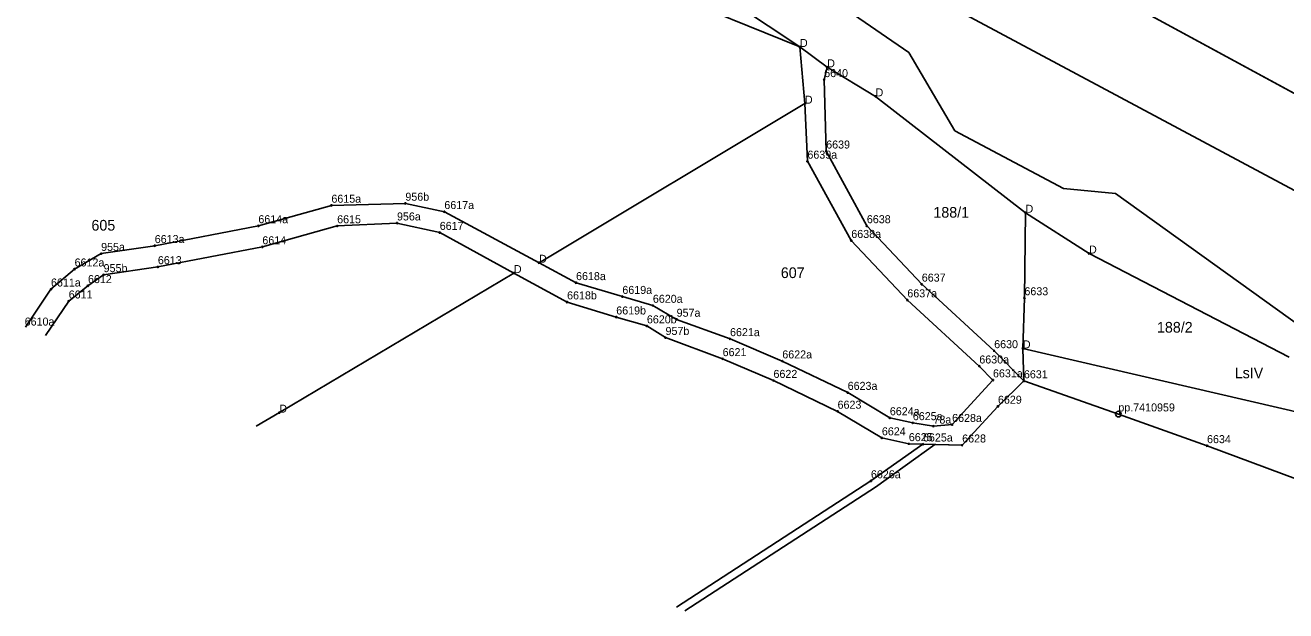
# Model space of a CAD drawing. Extents: x 7465393 to 7466459, y 5491258 to 5492404.
# Drawn here: x 7466057.8 to 7466235, y 5491369 to 5491451.3 of the extents above; entities that cross this region are included whole.
import ezdxf

# ---------------------------------------------------------------- set-up
doc = ezdxf.new("R2010")
doc.units = 0
for name, color, linetype in [('202-punkt graniczny', 7, 'Continuous'), ('202-punkt graniczny-Atr103', 7, 'Continuous'), ('203-punkt graniczny', 7, 'Continuous'), ('203-punkt graniczny-Atr103', 7, 'Continuous'), ('209-oznaczenie konturu klasyfikacyjnego', 7, 'Continuous'), ('211-numer działki ewidencyjnej', 7, 'Continuous'), ('217-kontur klasyfikacyjny', 7, 'Continuous'), ('218-kontur użytku gruntowego', 7, 'Continuous'), ('219-działka ewidencyjna', 7, 'Continuous')]:
    doc.layers.add(name, color=color, linetype=linetype)

# ---------------------------------------------------------------- blocks, each defined once
blk = doc.blocks.new('203')
blk.add_circle((0, 0), 0.09)
blk = doc.blocks.new('202')
blk.add_circle((0, 0), 0.4)

msp = doc.modelspace()

# ---------------------------------------------------------------- linework, layer by layer
at = {"layer": '217-kontur klasyfikacyjny'}
for points in [[(7466166.73, 5491448.28), (7466148.91, 5491460.14)], [(7466208.93, 5491456.57), (7466244.38, 5491437.34)], [(7466167.43, 5491440.31), (7466166.73, 5491448.28)], [(7466170.57, 5491445.42), (7466170.14, 5491443.67)], [(7466177.37, 5491441.33), (7466170.57, 5491445.42)], [(7466170.14, 5491443.67), (7466170.42, 5491433.63)], [(7466167.78, 5491432.2), (7466167.43, 5491440.31)], [(7466198.45, 5491424.97), (7466177.37, 5491441.33)], [(7466170.42, 5491433.63), (7466176.14, 5491423.12)], [(7466173.95, 5491421.06), (7466167.78, 5491432.2)], [(7466090.58, 5491423.12), (7466100.85, 5491426)], [(7466100.85, 5491426), (7466111.25, 5491426.28)], [(7466111.25, 5491426.28), (7466116.73, 5491425.11)], [(7466116.73, 5491425.11), (7466130.04, 5491417.94)], [(7466207.38, 5491419.24), (7466198.45, 5491424.97)], [(7466076.01, 5491420.33), (7466090.58, 5491423.12)], [(7466101.66, 5491423.11), (7466091.14, 5491420.17)], [(7466110.07, 5491423.52), (7466101.66, 5491423.11)], [(7466116.08, 5491422.18), (7466110.07, 5491423.52)], [(7466126.51, 5491416.49), (7466116.08, 5491422.18)], [(7466176.14, 5491423.12), (7466183.86, 5491414.91)], [(7466068.47, 5491419.22), (7466076.01, 5491420.33)], [(7466091.14, 5491420.17), (7466076.45, 5491417.36)], [(7466181.83, 5491412.7), (7466173.95, 5491421.06)], [(7466064.74, 5491417.05), (7466068.47, 5491419.22)], [(7466235.52, 5491404.67), (7466207.38, 5491419.24)], [(7466061.42, 5491414.22), (7466064.74, 5491417.05)], [(7466076.45, 5491417.36), (7466068.82, 5491416.24)], [(7466130.04, 5491417.94), (7466135.25, 5491415.13)], [(7466068.82, 5491416.24), (7466066.62, 5491414.71)], [(7466133.99, 5491412.41), (7466126.51, 5491416.49)], [(7466135.25, 5491415.13), (7466141.76, 5491413.18)], [(7466183.86, 5491414.91), (7466194.04, 5491405.56)], [(7466057.83, 5491408.9), (7466061.42, 5491414.22)], [(7466066.62, 5491414.71), (7466063.91, 5491412.54)], [(7466141.76, 5491413.18), (7466146.05, 5491411.93)], [(7466063.91, 5491412.54), (7466060.64, 5491407.69)], [(7466140.9, 5491410.3), (7466133.99, 5491412.41)], [(7466146.05, 5491411.93), (7466149.39, 5491409.97)], [(7466191.95, 5491403.4), (7466181.83, 5491412.7)], [(7466145.21, 5491409.05), (7466140.9, 5491410.3)], [(7466149.39, 5491409.97), (7466156.9, 5491407.24)], [(7466147.83, 5491407.41), (7466145.21, 5491409.05)], [(7466155.86, 5491404.43), (7466147.83, 5491407.41)], [(7466156.9, 5491407.24), (7466164.25, 5491404.11)], [(7466163.01, 5491401.38), (7466155.86, 5491404.43)], [(7466194.04, 5491405.56), (7466198.22, 5491401.32)], [(7466164.25, 5491404.11), (7466173.44, 5491399.69)], [(7466193.87, 5491401.45), (7466191.95, 5491403.4)], [(7466172.02, 5491397.05), (7466163.01, 5491401.38)], [(7466188.13, 5491395.18), (7466193.87, 5491401.45)], [(7466198.22, 5491401.32), (7466211.5, 5491396.66)], [(7466173.44, 5491399.69), (7466179.37, 5491396.13)], [(7466178.25, 5491393.31), (7466172.02, 5491397.05)], [(7466179.37, 5491396.13), (7466182.6, 5491395.43)], [(7466182.6, 5491395.43), (7466185.5, 5491394.96)], [(7466211.5, 5491396.66), (7466223.97, 5491392.21)], [(7466185.5, 5491394.96), (7466188.13, 5491395.18)], [(7466176.71, 5491387.27), (7466184.03, 5491392.43)], [(7466182.04, 5491392.48), (7466178.25, 5491393.31)], [(7466184.03, 5491392.43), (7466182.04, 5491392.48)], [(7466223.97, 5491392.21), (7466240.84, 5491385.94)], [(7466149.35, 5491369.53), (7466176.71, 5491387.27)]]:
    msp.add_lwpolyline(points, dxfattribs=at)
at = {"layer": '218-kontur użytku gruntowego'}
for points in [[(7466243.1, 5491424.43), (7466171.64, 5491462.69)], [(7466166.73, 5491448.28), (7466148.91, 5491460.14)], [(7466208.93, 5491456.57), (7466244.38, 5491437.34)], [(7466173.49, 5491453.36), (7466182.05, 5491447.52)], [(7466170.57, 5491445.42), (7466166.73, 5491448.28)], [(7466166.73, 5491448.28), (7466167.43, 5491440.31)], [(7466182.05, 5491447.52), (7466188.53, 5491436.49)], [(7466170.57, 5491445.42), (7466170.14, 5491443.67)], [(7466177.37, 5491441.33), (7466170.57, 5491445.42)], [(7466170.14, 5491443.67), (7466170.42, 5491433.63)], [(7466167.43, 5491440.31), (7466167.78, 5491432.2)], [(7466198.45, 5491424.97), (7466177.37, 5491441.33)], [(7466188.53, 5491436.49), (7466203.8, 5491428.37)], [(7466170.42, 5491433.63), (7466176.14, 5491423.12)], [(7466167.78, 5491432.2), (7466173.95, 5491421.06)], [(7466203.8, 5491428.37), (7466211.1, 5491427.7)], [(7466211.1, 5491427.7), (7466239.05, 5491407.62)], [(7466100.85, 5491426), (7466090.58, 5491423.12)], [(7466111.25, 5491426.28), (7466100.85, 5491426)], [(7466116.73, 5491425.11), (7466111.25, 5491426.28)], [(7466130.04, 5491417.94), (7466116.73, 5491425.11)], [(7466207.38, 5491419.24), (7466198.45, 5491424.97)], [(7466090.58, 5491423.12), (7466076.01, 5491420.33)], [(7466101.66, 5491423.11), (7466091.14, 5491420.17)], [(7466110.07, 5491423.52), (7466101.66, 5491423.11)], [(7466116.08, 5491422.18), (7466110.07, 5491423.52)], [(7466126.51, 5491416.49), (7466116.08, 5491422.18)], [(7466176.14, 5491423.12), (7466183.86, 5491414.91)], [(7466076.01, 5491420.33), (7466068.47, 5491419.22)], [(7466091.14, 5491420.17), (7466076.45, 5491417.36)], [(7466173.95, 5491421.06), (7466181.83, 5491412.7)], [(7466068.47, 5491419.22), (7466064.74, 5491417.05)], [(7466235.52, 5491404.67), (7466207.38, 5491419.24)], [(7466064.74, 5491417.05), (7466061.42, 5491414.22)], [(7466076.45, 5491417.36), (7466068.82, 5491416.24)], [(7466135.25, 5491415.13), (7466130.04, 5491417.94)], [(7466068.82, 5491416.24), (7466066.62, 5491414.71)], [(7466133.99, 5491412.41), (7466126.51, 5491416.49)], [(7466141.76, 5491413.18), (7466135.25, 5491415.13)], [(7466183.86, 5491414.91), (7466194.04, 5491405.56)], [(7466061.42, 5491414.22), (7466057.83, 5491408.9)], [(7466066.62, 5491414.71), (7466063.91, 5491412.54)], [(7466146.05, 5491411.93), (7466141.76, 5491413.18)], [(7466063.91, 5491412.54), (7466060.64, 5491407.69)], [(7466140.9, 5491410.3), (7466133.99, 5491412.41)], [(7466149.39, 5491409.97), (7466146.05, 5491411.93)], [(7466181.83, 5491412.7), (7466191.95, 5491403.4)], [(7466145.21, 5491409.05), (7466140.9, 5491410.3)], [(7466156.9, 5491407.24), (7466149.39, 5491409.97)], [(7466147.83, 5491407.41), (7466145.21, 5491409.05)], [(7466155.86, 5491404.43), (7466147.83, 5491407.41)], [(7466164.25, 5491404.11), (7466156.9, 5491407.24)], [(7466163.01, 5491401.38), (7466155.86, 5491404.43)], [(7466194.04, 5491405.56), (7466198.22, 5491401.32)], [(7466173.44, 5491399.69), (7466164.25, 5491404.11)], [(7466191.95, 5491403.4), (7466193.87, 5491401.45)], [(7466172.02, 5491397.05), (7466163.01, 5491401.38)], [(7466193.87, 5491401.45), (7466188.13, 5491395.18)], [(7466198.22, 5491401.32), (7466194.57, 5491397.75)], [(7466179.37, 5491396.13), (7466173.44, 5491399.69)], [(7466194.57, 5491397.75), (7466189.54, 5491392.29)], [(7466178.25, 5491393.31), (7466172.02, 5491397.05)], [(7466182.6, 5491395.43), (7466179.37, 5491396.13)], [(7466185.5, 5491394.96), (7466182.6, 5491395.43)], [(7466188.13, 5491395.18), (7466185.5, 5491394.96)], [(7466184.03, 5491392.43), (7466176.71, 5491387.27)], [(7466177.35, 5491386.39), (7466185.7, 5491392.39)], [(7466182.04, 5491392.48), (7466178.25, 5491393.31)], [(7466184.03, 5491392.43), (7466182.04, 5491392.48)], [(7466185.7, 5491392.39), (7466184.03, 5491392.43)], [(7466189.54, 5491392.29), (7466185.7, 5491392.39)], [(7466176.71, 5491387.27), (7466149.35, 5491369.53)], [(7466150.55, 5491369.01), (7466177.35, 5491386.39)]]:
    msp.add_lwpolyline(points, dxfattribs=at)
at = {"layer": '219-działka ewidencyjna'}
for points in [[(7466171.64, 5491462.69), (7466243.1, 5491424.43)], [(7466147.45, 5491456.12), (7466166.73, 5491448.28)], [(7466208.93, 5491456.57), (7466251.84, 5491433.3)], [(7466166.73, 5491448.28), (7466167.43, 5491440.31)], [(7466166.73, 5491448.28), (7466170.57, 5491445.42)], [(7466170.57, 5491445.42), (7466170.14, 5491443.67)], [(7466170.57, 5491445.42), (7466177.37, 5491441.33)], [(7466170.14, 5491443.67), (7466170.42, 5491433.63)], [(7466130.04, 5491417.94), (7466167.43, 5491440.31)], [(7466167.43, 5491440.31), (7466167.78, 5491432.2)], [(7466177.37, 5491441.33), (7466198.45, 5491424.97)], [(7466170.42, 5491433.63), (7466176.14, 5491423.12)], [(7466167.78, 5491432.2), (7466173.95, 5491421.06)], [(7466090.58, 5491423.12), (7466100.85, 5491426)], [(7466100.85, 5491426), (7466111.25, 5491426.28)], [(7466111.25, 5491426.28), (7466116.73, 5491425.11)], [(7466130.04, 5491417.94), (7466116.73, 5491425.11)], [(7466198.45, 5491424.97), (7466198.29, 5491412.99)], [(7466198.45, 5491424.97), (7466207.38, 5491419.24)], [(7466076.01, 5491420.33), (7466090.58, 5491423.12)], [(7466091.14, 5491420.17), (7466101.66, 5491423.11)], [(7466101.66, 5491423.11), (7466110.07, 5491423.52)], [(7466110.07, 5491423.52), (7466116.08, 5491422.18)], [(7466126.51, 5491416.49), (7466116.08, 5491422.18)], [(7466176.14, 5491423.12), (7466183.86, 5491414.91)], [(7466068.47, 5491419.22), (7466076.01, 5491420.33)], [(7466076.45, 5491417.36), (7466091.14, 5491420.17)], [(7466173.95, 5491421.06), (7466181.83, 5491412.7)], [(7466064.74, 5491417.05), (7466068.47, 5491419.22)], [(7466207.38, 5491419.24), (7466235.52, 5491404.67)], [(7466061.42, 5491414.22), (7466064.74, 5491417.05)], [(7466068.82, 5491416.24), (7466076.45, 5491417.36)], [(7466130.04, 5491417.94), (7466135.25, 5491415.13)], [(7466066.62, 5491414.71), (7466068.82, 5491416.24)], [(7466093.53, 5491396.87), (7466126.51, 5491416.49)], [(7466126.51, 5491416.49), (7466133.99, 5491412.41)], [(7466135.25, 5491415.13), (7466141.76, 5491413.18)], [(7466183.86, 5491414.91), (7466194.04, 5491405.56)], [(7466057.83, 5491408.9), (7466061.42, 5491414.22)], [(7466063.91, 5491412.54), (7466066.62, 5491414.71)], [(7466141.76, 5491413.18), (7466146.05, 5491411.93)], [(7466060.64, 5491407.69), (7466063.91, 5491412.54)], [(7466133.99, 5491412.41), (7466140.9, 5491410.3)], [(7466146.05, 5491411.93), (7466149.39, 5491409.97)], [(7466181.83, 5491412.7), (7466191.95, 5491403.4)], [(7466198.08, 5491405.9), (7466198.29, 5491412.99)], [(7466140.9, 5491410.3), (7466145.21, 5491409.05)], [(7466149.39, 5491409.97), (7466156.9, 5491407.24)], [(7466145.21, 5491409.05), (7466147.83, 5491407.41)], [(7466147.83, 5491407.41), (7466155.86, 5491404.43)], [(7466156.9, 5491407.24), (7466164.25, 5491404.11)], [(7466155.86, 5491404.43), (7466163.01, 5491401.38)], [(7466194.04, 5491405.56), (7466198.22, 5491401.32)], [(7466198.08, 5491405.9), (7466198.22, 5491401.32)], [(7466198.08, 5491405.9), (7466241.56, 5491395.8)], [(7466164.25, 5491404.11), (7466173.44, 5491399.69)], [(7466191.95, 5491403.4), (7466193.87, 5491401.45)], [(7466163.01, 5491401.38), (7466172.02, 5491397.05)], [(7466188.13, 5491395.18), (7466193.87, 5491401.45)], [(7466194.57, 5491397.75), (7466198.22, 5491401.32)], [(7466198.22, 5491401.32), (7466211.5, 5491396.66)], [(7466173.44, 5491399.69), (7466179.37, 5491396.13)], [(7466189.54, 5491392.29), (7466194.57, 5491397.75)], [(7466090.25, 5491394.95), (7466093.53, 5491396.87)], [(7466172.02, 5491397.05), (7466178.25, 5491393.31)], [(7466179.37, 5491396.13), (7466182.6, 5491395.43)], [(7466182.6, 5491395.43), (7466185.5, 5491394.96)], [(7466211.5, 5491396.66), (7466223.97, 5491392.21)], [(7466185.5, 5491394.96), (7466188.13, 5491395.18)], [(7466176.71, 5491387.27), (7466184.03, 5491392.43)], [(7466178.25, 5491393.31), (7466182.04, 5491392.48)], [(7466182.04, 5491392.48), (7466184.03, 5491392.43)], [(7466189.54, 5491392.29), (7466184.03, 5491392.43)], [(7466223.97, 5491392.21), (7466240.84, 5491385.94)], [(7466149.35, 5491369.53), (7466176.71, 5491387.27)]]:
    msp.add_lwpolyline(points, dxfattribs=at)

# ---------------------------------------------------------------- block references
at = {"layer": '202-punkt graniczny'}
msp.add_blockref('202', (7466211.5, 5491396.66), dxfattribs=at)
at = {"layer": '203-punkt graniczny'}
for p in [(7466166.73, 5491448.28), (7466170.57, 5491445.42), (7466170.14, 5491443.67), (7466177.37, 5491441.33), (7466167.43, 5491440.31), (7466170.42, 5491433.63), (7466167.78, 5491432.2), (7466100.85, 5491426), (7466111.25, 5491426.28), (7466116.73, 5491425.11), (7466198.45, 5491424.97), (7466090.58, 5491423.12), (7466101.66, 5491423.11), (7466110.07, 5491423.52), (7466116.08, 5491422.18), (7466176.14, 5491423.12), (7466076.01, 5491420.33), (7466091.14, 5491420.17), (7466173.95, 5491421.06), (7466068.47, 5491419.22), (7466207.38, 5491419.24), (7466064.74, 5491417.05), (7466076.45, 5491417.36), (7466126.51, 5491416.49), (7466130.04, 5491417.94), (7466066.62, 5491414.71), (7466068.82, 5491416.24), (7466135.25, 5491415.13), (7466183.86, 5491414.91), (7466061.42, 5491414.22), (7466141.76, 5491413.18), (7466198.29, 5491412.99), (7466063.91, 5491412.54), (7466133.99, 5491412.41), (7466146.05, 5491411.93), (7466181.83, 5491412.7), (7466140.9, 5491410.3), (7466149.39, 5491409.97), (7466145.21, 5491409.05), (7466147.83, 5491407.41), (7466156.9, 5491407.24), (7466198.08, 5491405.9), (7466155.86, 5491404.43), (7466164.25, 5491404.11), (7466194.04, 5491405.56), (7466191.95, 5491403.4), (7466163.01, 5491401.38), (7466193.87, 5491401.45), (7466198.22, 5491401.32), (7466173.44, 5491399.69), (7466172.02, 5491397.05), (7466194.57, 5491397.75), (7466093.53, 5491396.87), (7466179.37, 5491396.13), (7466182.6, 5491395.43), (7466185.5, 5491394.96), (7466188.13, 5491395.18), (7466178.25, 5491393.31), (7466182.04, 5491392.48), (7466184.03, 5491392.43), (7466189.54, 5491392.29), (7466223.97, 5491392.21), (7466176.71, 5491387.27)]:
    msp.add_blockref('203', p, dxfattribs=at)

# ---------------------------------------------------------------- texts
at = {"layer": '202-punkt graniczny-Atr103'}
msp.add_text('pp.7410959', height=1.125, dxfattribs=at).set_placement((7466211.5, 5491397.04))
at = {"layer": '203-punkt graniczny-Atr103'}
for s, height, p in [('D', 1.12, (7466166.73, 5491448.28)), ('6640', 1.125, (7466170.14, 5491444.04)), ('D', 1.12, (7466170.57, 5491445.42)), ('D', 1.12, (7466167.43, 5491440.31)), ('D', 1.12, (7466177.37, 5491441.33)), ('6639', 1.125, (7466170.42, 5491434)), ('6639a', 1.125, (7466167.78, 5491432.58)), ('6615a', 1.125, (7466100.85, 5491426.38)), ('956b', 1.125, (7466111.25, 5491426.66)), ('6617a', 1.125, (7466116.73, 5491425.49)), ('D', 1.12, (7466198.45, 5491424.97)), ('6614a', 1.125, (7466090.58, 5491423.5)), ('6615', 1.125, (7466101.66, 5491423.49)), ('956a', 1.125, (7466110.07, 5491423.89)), ('6617', 1.125, (7466116.08, 5491422.56)), ('6638', 1.125, (7466176.14, 5491423.5)), ('6638a', 1.125, (7466173.95, 5491421.43)), ('955a', 1.125, (7466068.47, 5491419.6)), ('6613a', 1.125, (7466076.01, 5491420.71)), ('6614', 1.125, (7466091.14, 5491420.54)), ('D', 1.12, (7466207.38, 5491419.24)), ('6612a', 1.125, (7466064.74, 5491417.42)), ('6613', 1.125, (7466076.45, 5491417.74)), ('D', 1.12, (7466130.04, 5491417.94)), ('955b', 1.125, (7466068.82, 5491416.62)), ('D', 1.12, (7466126.51, 5491416.49)), ('6618a', 1.125, (7466135.25, 5491415.5)), ('6611a', 1.125, (7466061.42, 5491414.6)), ('6612', 1.125, (7466066.62, 5491415.08)), ('6637', 1.125, (7466183.86, 5491415.29)), ('6611', 1.125, (7466063.91, 5491412.92)), ('6618b', 1.125, (7466133.99, 5491412.79)), ('6619a', 1.125, (7466141.76, 5491413.56)), ('6620a', 1.125, (7466146.05, 5491412.31)), ('6637a', 1.125, (7466181.83, 5491413.08)), ('6633', 1.125, (7466198.29, 5491413.37)), ('6619b', 1.125, (7466140.9, 5491410.67)), ('957a', 1.125, (7466149.39, 5491410.35)), ('6610a', 1.125, (7466057.72, 5491409.11)), ('6620b', 1.125, (7466145.21, 5491409.42)), ('957b', 1.125, (7466147.83, 5491407.79)), ('6621a', 1.125, (7466156.9, 5491407.62)), ('6621', 1.125, (7466155.86, 5491404.81)), ('6630', 1.125, (7466194.04, 5491405.93)), ('D', 1.12, (7466198.08, 5491405.9)), ('6622a', 1.125, (7466164.25, 5491404.49)), ('6630a', 1.125, (7466191.95, 5491403.78)), ('6622', 1.125, (7466163.01, 5491401.75)), ('6631a', 1.125, (7466193.87, 5491401.83)), ('6631', 1.125, (7466198.22, 5491401.7)), ('6623a', 1.125, (7466173.44, 5491400.07)), ('6629', 1.125, (7466194.57, 5491398.12)), ('D', 1.12, (7466093.53, 5491396.87)), ('6623', 1.125, (7466172.02, 5491397.42)), ('6624a', 1.125, (7466179.37, 5491396.5)), ('6625a', 1.125, (7466182.6, 5491395.81)), ('78a', 1.125, (7466185.5, 5491395.33)), ('6628a', 1.125, (7466188.13, 5491395.56)), ('6624', 1.125, (7466178.25, 5491393.68)), ('6625', 1.125, (7466182.04, 5491392.86)), ('6625a', 1.125, (7466184.03, 5491392.81)), ('6628', 1.125, (7466189.54, 5491392.67)), ('6634', 1.125, (7466223.97, 5491392.58)), ('6626a', 1.125, (7466176.71, 5491387.64))]:
    msp.add_text(s, height=height, dxfattribs=at).set_placement(p)
at = {"layer": '209-oznaczenie konturu klasyfikacyjnego'}
msp.add_text('LsIV', height=1.5, dxfattribs=at).set_placement((7466227.86, 5491401.71))
at = {"layer": '211-numer działki ewidencyjnej'}
for s, p in [('188/1', (7466185.49, 5491424.28)), ('605', (7466067.11, 5491422.46)), ('607', (7466164.04, 5491415.79)), ('188/2', (7466216.93, 5491408.12))]:
    msp.add_text(s, height=1.5, dxfattribs=at).set_placement(p)

doc.saveas('drawing.dxf')
